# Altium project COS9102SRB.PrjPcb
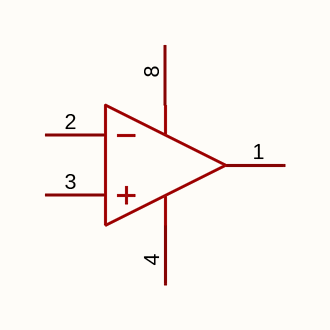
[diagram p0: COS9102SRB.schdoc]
1 sheet, 1 parts. Net scope: global (net labels, ports and power ports of the same name join across sheets).

## Sheet COS9102SRB.schdoc
size 127 x 101 mm

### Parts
U?  cos9102srb  [SOP-8_L4.9-W3.9-P1.27-LS6.0-BL]  (value not drawn)  (part A of 2)

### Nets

Not connected (* = marked no-connect by the designer): U? 1(OUT_A) 2(IN_A-) 3(IN_A+) 4(V-) 8(V+)

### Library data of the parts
U? = cos9102srb: 放大器数:2;轨到轨:轨到轨输入,轨到轨输出;增益带宽积(GBW):1MHz;输入失调电压(Vos):5mV;压摆率(SR):800V/ms;输入偏置电流(Ib):1pA;; Manufacturer: COSINE(科山芯创); AddInBom: yes; ModelId: 75c24a7891ee4dd6bdac16a7163ff87e; ModelName: SOP-8_L4.9-W3.9-P1.27-LS6.0-BL-1; ModelTransform: 192.913,236.22,0,0,0,0,-0.393,2.749,0; Number of Channels: 2; Gain Bandwidth Product: 1MHz; Vos - Input Offset Voltage: 5mV; Input Offset Voltage Drift(Vos TC): 1uV/℃; Ib - Input Bias Current: 1pA; Input Voltage Noise Density: 40nV/√Hz@1kHz; Common Mode Rejection Ratio(CMRR): 125dB; Quiescent Current: 80uA; Output Current: 50mA; Single supply: 2.7V~16V; Dual Supply: -8V~-1.35V；1.35V~8V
